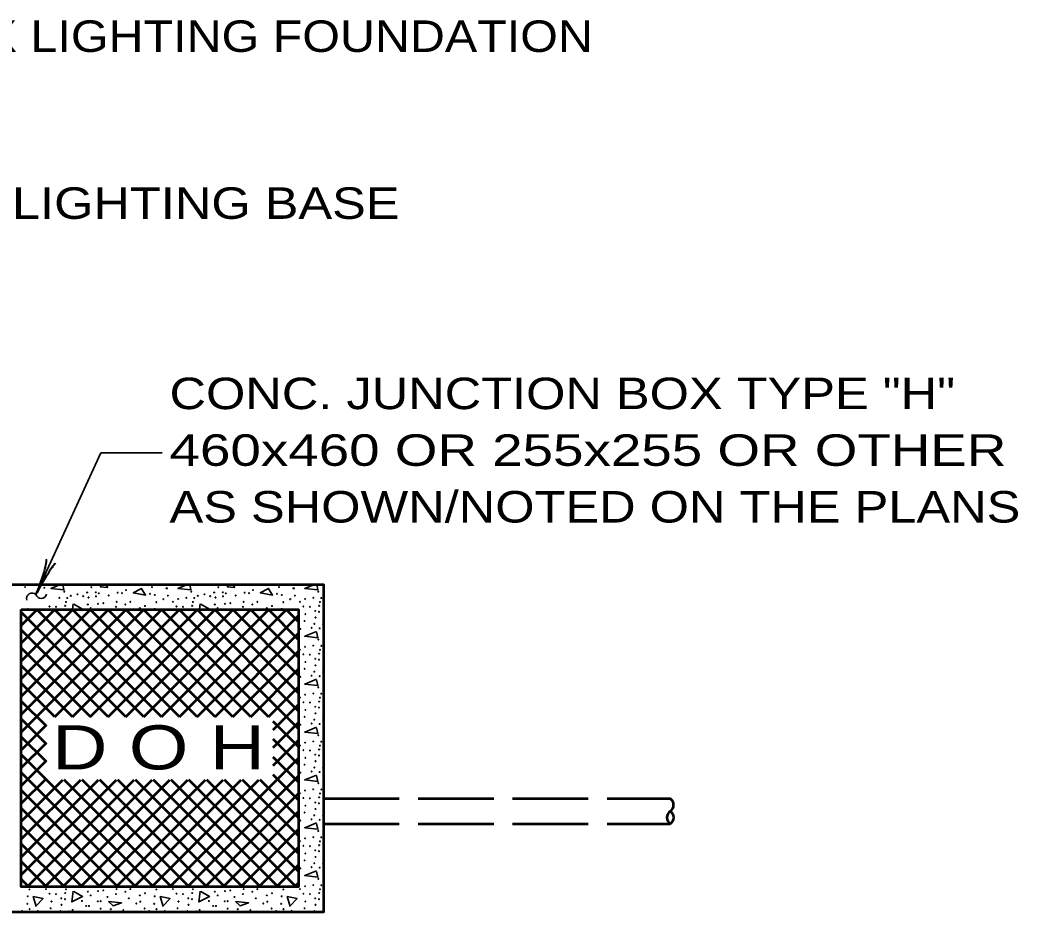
# Model space of a CAD drawing. Extents: x -24 to 689, y -7 to 446.
# Drawn here: x 391.4 to 470.6, y 78.6 to 149.4 of the extents above; entities that cross this region are included whole.
import ezdxf
from ezdxf.enums import TextEntityAlignment as Align

# ---------------------------------------------------------------- set-up
doc = ezdxf.new("R2010")
doc.units = 0
doc.linetypes.add('LONG_DASHED', pattern=[7.5, 6, -1.5])
doc.layers.add('1', color=7, linetype='Continuous', lineweight=35)

msp = doc.modelspace()

# ---------------------------------------------------------------- linework, layer by layer
at = {"layer": '1'}
for p, q in [((392.647, 103.805), (397.796, 115.046)), ((402.654, 115.046), (397.796, 115.046)), ((395.546, 102.608), (395.61, 103.056)), ((405.626, 102.608), (405.69, 103.056))]:
    msp.add_line(p, q, dxfattribs=at)
at = {"layer": '1', "lineweight": 53}
for p, q in [((391.486, 101.358), (392.736, 102.608)), ((391.486, 99.944), (394.15, 102.608)), ((391.486, 98.53), (395.564, 102.608)), ((391.486, 97.115), (396.979, 102.608)), ((391.486, 95.701), (398.393, 102.608)), ((391.486, 94.287), (399.807, 102.608)), ((391.486, 92.873), (401.221, 102.608)), ((399.795, 94.108), (391.486, 102.418)), ((401.21, 94.108), (392.71, 102.608)), ((402.624, 94.108), (394.124, 102.608)), ((394.135, 94.108), (402.635, 102.608)), ((404.038, 94.108), (395.538, 102.608)), ((395.55, 94.108), (404.05, 102.608)), ((405.452, 94.108), (396.952, 102.608)), ((396.964, 94.108), (405.464, 102.608)), ((406.866, 94.108), (398.366, 102.608)), ((398.378, 94.108), (406.878, 102.608)), ((408.281, 94.108), (399.781, 102.608)), ((399.792, 94.108), (408.292, 102.608)), ((409.695, 94.108), (401.195, 102.608)), ((401.207, 94.108), (409.707, 102.608)), ((411.109, 94.108), (402.609, 102.608)), ((402.621, 94.108), (411.121, 102.608)), ((413.486, 93.146), (404.023, 102.608)), ((404.035, 94.108), (412.535, 102.608)), ((413.486, 94.56), (405.438, 102.608)), ((413.486, 95.974), (406.852, 102.608)), ((413.486, 97.388), (408.266, 102.608)), ((413.486, 98.803), (409.68, 102.608)), ((413.486, 100.217), (411.094, 102.608)), ((413.486, 101.631), (412.509, 102.608)), ((405.449, 94.108), (413.486, 102.145)), ((398.381, 94.108), (391.486, 101.004)), ((406.863, 94.108), (413.486, 100.731)), ((396.967, 94.108), (391.486, 99.589)), ((408.278, 94.108), (413.486, 99.317)), ((395.553, 94.108), (391.486, 98.175)), ((409.692, 94.108), (413.486, 97.902)), ((394.138, 94.108), (391.486, 96.761)), ((411.106, 94.108), (413.486, 96.488)), ((393.486, 93.347), (391.486, 95.347)), ((411.486, 93.074), (413.486, 95.074)), ((393.486, 91.933), (391.486, 93.933)), ((413.486, 91.732), (411.486, 93.732)), ((411.486, 91.66), (413.486, 93.66)), ((391.486, 91.459), (393.486, 93.459)), ((393.486, 90.518), (391.486, 92.518)), ((391.486, 90.044), (393.486, 92.044)), ((413.486, 90.317), (411.486, 92.317)), ((411.486, 90.245), (413.486, 92.245)), ((401.982, 80.608), (391.486, 91.104)), ((391.486, 88.63), (393.486, 90.63)), ((403.263, 80.608), (413.486, 90.831)), ((413.486, 88.903), (411.486, 90.903)), ((400.567, 80.608), (391.486, 89.69)), ((391.486, 87.216), (393.486, 89.216)), ((391.486, 85.802), (394.792, 89.108)), ((391.486, 84.388), (396.207, 89.108)), ((391.486, 82.973), (397.621, 89.108)), ((391.486, 81.559), (399.035, 89.108)), ((391.949, 80.608), (400.449, 89.108)), ((393.363, 80.608), (401.863, 89.108)), ((394.778, 80.608), (403.278, 89.108)), ((403.396, 80.608), (394.896, 89.108)), ((396.192, 80.608), (404.692, 89.108)), ((404.81, 80.608), (396.31, 89.108)), ((397.606, 80.608), (406.106, 89.108)), ((406.224, 80.608), (397.724, 89.108)), ((399.02, 80.608), (407.52, 89.108)), ((407.638, 80.608), (399.138, 89.108)), ((400.435, 80.608), (408.935, 89.108)), ((409.053, 80.608), (400.553, 89.108)), ((401.849, 80.608), (410.349, 89.108)), ((410.467, 80.608), (401.967, 89.108)), ((411.881, 80.608), (403.381, 89.108)), ((404.677, 80.608), (413.486, 89.417)), ((413.295, 80.608), (404.795, 89.108)), ((413.486, 81.832), (406.21, 89.108)), ((413.486, 83.246), (407.624, 89.108)), ((413.486, 84.66), (409.038, 89.108)), ((413.486, 86.075), (410.452, 89.108)), ((413.486, 87.489), (411.486, 89.489)), ((399.153, 80.608), (391.486, 88.276)), ((406.091, 80.608), (413.486, 88.003)), ((397.739, 80.608), (391.486, 86.861)), ((407.506, 80.608), (413.486, 86.589)), ((396.325, 80.608), (391.486, 85.447)), ((408.92, 80.608), (413.486, 85.174)), ((394.911, 80.608), (391.486, 84.033)), ((410.334, 80.608), (413.486, 83.76)), ((393.496, 80.608), (391.486, 82.619)), ((411.748, 80.608), (413.486, 82.346)), ((392.082, 80.608), (391.486, 81.205)), ((413.162, 80.608), (413.486, 80.932))]:
    msp.add_line(p, q, dxfattribs=at)
at = {"layer": '1', "linetype": 'LONG_DASHED', "lineweight": 53}
for p, q in [((415.486, 87.608), (442.986, 87.608)), ((415.486, 85.608), (442.986, 85.608))]:
    msp.add_line(p, q, dxfattribs=at)
at = {"layer": '1', "lineweight": 53}
for points in [[(389.486, 78.608), (389.486, 104.608), (415.486, 104.608), (415.486, 78.608)], [(391.486, 102.608), (413.486, 102.608), (413.486, 80.608), (391.486, 80.608)]]:
    msp.add_lwpolyline(points, close=True, dxfattribs=at)
at = {"layer": '1'}
for points in [[(394.602, 104.608), (393.83, 104.296), (394.87, 104.176), (394.776, 104.608)], [(397.933, 104.608), (397.75, 104.416), (398.33, 104.376), (398.214, 104.608)], [(404.682, 104.608), (403.91, 104.296), (404.95, 104.176), (404.856, 104.608)], [(408.012, 104.608), (407.83, 104.416), (408.41, 104.376), (408.294, 104.608)], [(414.762, 104.608), (413.99, 104.296), (415.03, 104.176), (414.936, 104.608)], [(401.03, 104.296), (400.37, 103.936), (401.35, 103.756), (400.99, 104.316)], [(411.11, 104.296), (410.45, 103.936), (411.43, 103.756), (411.07, 104.316)], [(395.65, 103.036), (396.35, 102.636), (396.293, 102.608)], [(405.73, 103.036), (406.43, 102.636), (406.373, 102.608)], [(392.438, 102.608), (392.43, 102.636), (392.566, 102.608)], [(402.518, 102.608), (402.51, 102.636), (402.646, 102.608)], [(412.598, 102.608), (412.59, 102.636), (412.726, 102.608)], [(414.93, 100.876), (413.99, 100.496), (415.03, 100.376), (414.93, 100.836)], [(414.93, 97.076), (413.99, 96.696), (415.03, 96.576), (414.93, 97.036)], [(414.93, 93.276), (413.99, 92.896), (415.03, 92.776), (414.93, 93.236)], [(414.93, 89.476), (413.99, 89.096), (415.03, 88.976), (414.93, 89.436)], [(414.93, 85.676), (413.99, 85.296), (415.03, 85.176), (414.93, 85.636)], [(414.93, 81.876), (413.99, 81.496), (415.03, 81.376), (414.93, 81.836)], [(395.65, 80.236), (396.35, 79.836), (395.49, 79.416), (395.61, 80.256)], [(405.73, 80.236), (406.43, 79.836), (405.57, 79.416), (405.69, 80.256)], [(392.67, 79.036), (392.43, 79.836), (393.21, 79.676), (392.65, 79.076)], [(402.75, 79.036), (402.51, 79.836), (403.29, 79.676), (402.73, 79.076)], [(412.83, 79.036), (412.59, 79.836), (413.37, 79.676), (412.81, 79.076)]]:
    msp.add_lwpolyline(points, dxfattribs=at)
for points in [[(398.41, 79.456), (399.45, 79.336), (398.77, 79.096)], [(408.49, 79.456), (409.53, 79.336), (408.85, 79.096)]]:
    msp.add_lwpolyline(points, close=True, dxfattribs=at)
for centre in [(395.534, 104.555), (396.369, 104.568), (405.614, 104.555), (406.449, 104.568), (391.784, 104.396), (392.923, 104.303), (393.315, 104.345), (394.898, 104.038), (395.945, 103.826), (396.714, 103.972), (397.045, 104.383), (397.403, 103.985), (397.636, 103.906), (399.133, 103.959), (399.478, 103.919), (399.796, 104.158), (401.705, 103.866), (401.864, 104.396), (402.089, 103.773), (403.003, 104.303), (403.056, 104.303), (404.978, 104.038), (406.025, 103.826), (406.794, 103.972), (407.125, 104.383), (407.483, 103.985), (407.716, 103.906), (409.213, 103.959), (409.558, 103.919), (409.876, 104.158), (411.785, 103.866), (411.944, 104.396), (412.169, 103.773), (413.083, 104.303), (413.136, 104.303), (415.058, 104.038), (394.5, 103.548), (395.031, 103.216), (395.137, 103.534), (395.415, 103.707), (396.396, 103.68), (396.767, 103.017), (396.82, 103.574), (397.416, 103.667), (397.575, 103.07), (397.994, 103.123), (398.418, 103.733), (399.054, 103.229), (399.743, 103.017), (400.141, 103.229), (402.208, 103.203), (402.752, 103.442), (403.123, 103.72), (403.52, 103.229), (403.931, 103.455), (404.58, 103.548), (405.111, 103.216), (405.217, 103.534), (405.495, 103.707), (406.476, 103.68), (406.847, 103.017), (406.9, 103.574), (407.496, 103.667), (407.655, 103.07), (408.074, 103.123), (408.498, 103.733), (409.134, 103.229), (409.823, 103.017), (410.221, 103.229), (412.288, 103.203), (412.832, 103.442), (413.203, 103.72), (413.6, 103.229), (414.011, 103.455), (414.66, 103.548), (415.191, 103.216), (415.297, 103.534), (391.996, 102.659), (393.719, 102.858), (394.235, 102.832), (394.964, 102.911), (396.992, 102.726), (399.001, 102.832), (400.896, 102.726), (401.307, 102.898), (402.076, 102.659), (403.799, 102.858), (404.315, 102.832), (405.044, 102.911), (407.072, 102.726), (409.081, 102.832), (410.976, 102.726), (411.387, 102.898), (412.156, 102.659), (413.879, 102.858), (414.038, 102.248), (414.395, 102.832), (414.819, 102.5), (415.111, 102.434), (415.124, 102.911), (413.971, 101.705), (414.74, 101.48), (414.833, 101.983), (415.442, 101.453), (413.64, 101.073), (414.528, 101.166), (415.164, 101.126), (415.058, 100.238), (413.6, 99.429), (413.879, 99.058), (414.011, 99.655), (414.395, 99.032), (414.66, 99.748), (415.124, 99.111), (415.191, 99.416), (415.297, 99.734), (414.038, 98.448), (414.819, 98.7), (415.111, 98.634), (413.971, 97.905), (414.74, 97.68), (414.833, 98.183), (415.442, 97.653), (413.64, 97.273), (414.528, 97.366), (415.164, 97.326), (414.011, 95.855), (414.66, 95.948), (415.058, 96.438), (415.297, 95.934), (413.6, 95.629), (413.879, 95.258), (414.395, 95.232), (415.124, 95.311), (415.191, 95.616), (414.038, 94.648), (414.819, 94.9), (414.833, 94.383), (415.111, 94.834), (413.64, 93.473), (413.971, 94.105), (414.528, 93.566), (414.74, 93.88), (415.164, 93.526), (415.442, 93.853), (414.011, 92.055), (414.66, 92.148), (415.058, 92.638), (415.297, 92.134), (413.6, 91.829), (413.879, 91.458), (414.395, 91.432), (414.819, 91.1), (415.124, 91.511), (415.191, 91.816), (413.971, 90.305), (414.038, 90.848), (414.833, 90.583), (415.111, 91.034), (413.64, 89.673), (414.528, 89.766), (414.74, 90.08), (415.164, 89.726), (415.442, 90.053), (415.058, 88.838), (413.6, 88.029), (414.011, 88.255), (414.66, 88.348), (415.191, 88.016), (415.297, 88.334), (413.879, 87.658), (414.395, 87.632), (414.819, 87.3), (415.111, 87.234), (415.124, 87.711), (413.971, 86.505), (414.038, 87.048), (414.833, 86.783), (413.64, 85.873), (414.528, 85.966), (414.74, 86.28), (415.164, 85.926), (415.442, 86.253), (415.058, 85.038), (413.6, 84.229), (414.011, 84.455), (414.66, 84.548), (415.191, 84.216), (415.297, 84.534), (413.879, 83.858), (414.038, 83.248), (414.395, 83.832), (414.819, 83.5), (415.111, 83.434), (415.124, 83.911), (413.971, 82.705), (414.74, 82.48), (414.833, 82.983), (415.442, 82.453), (413.64, 82.073), (414.528, 82.166), (415.164, 82.126), (415.058, 81.238), (392.128, 80.403), (393.44, 80.429), (393.719, 80.058), (394.235, 80.032), (394.964, 80.111), (395.031, 80.416), (396.767, 80.217), (397.575, 80.27), (397.994, 80.323), (399.001, 80.032), (399.054, 80.429), (399.743, 80.217), (400.141, 80.429), (401.307, 80.098), (402.208, 80.403), (403.52, 80.429), (403.799, 80.058), (404.315, 80.032), (405.044, 80.111), (405.111, 80.416), (406.847, 80.217), (407.655, 80.27), (408.074, 80.323), (409.081, 80.032), (409.134, 80.429), (409.823, 80.217), (410.221, 80.429), (411.387, 80.098), (412.288, 80.403), (413.6, 80.429), (413.879, 80.058), (414.011, 80.655), (414.395, 80.032), (414.66, 80.748), (415.124, 80.111), (415.191, 80.416), (415.297, 80.734), (391.956, 79.263), (391.996, 79.859), (393.878, 79.448), (394.659, 79.7), (394.951, 79.634), (396.303, 79.488), (396.992, 79.926), (397.555, 79.459), (397.782, 79.475), (398.325, 79.806), (400.021, 79.7), (400.618, 79.289), (400.896, 79.926), (400.936, 79.435), (402.036, 79.263), (402.076, 79.859), (403.958, 79.448), (404.739, 79.7), (405.031, 79.634), (406.383, 79.488), (407.072, 79.926), (407.635, 79.459), (407.862, 79.475), (408.405, 79.806), (410.101, 79.7), (410.698, 79.289), (410.976, 79.926), (411.016, 79.435), (412.116, 79.263), (412.156, 79.859), (414.038, 79.448), (414.819, 79.7), (415.111, 79.634), (391.558, 78.693), (392.141, 78.839), (392.791, 78.693), (393.811, 78.905), (394.58, 78.68), (394.673, 79.183), (395.282, 78.653), (395.561, 78.772), (396.634, 79.09), (396.86, 79.09), (397.782, 78.878), (398.59, 78.839), (399.584, 78.759), (401.28, 78.892), (401.638, 78.693), (402.221, 78.839), (402.871, 78.693), (403.891, 78.905), (404.66, 78.68), (404.753, 79.183), (405.362, 78.653), (405.641, 78.772), (406.714, 79.09), (406.94, 79.09), (407.862, 78.878), (408.67, 78.839), (409.664, 78.759), (411.36, 78.892), (411.718, 78.693), (412.301, 78.839), (412.951, 78.693), (413.971, 78.905), (414.74, 78.68), (414.833, 79.183), (415.442, 78.653)]:
    msp.add_circle(centre, 0.0265, dxfattribs=at)
for centre, radius, start, end in [((391.624, 104.608), 0.0265, 179.8468, 0.1532), ((392.3, 104.608), 0.0265, 179.8468, 0.1532), ((401.704, 104.608), 0.0265, 179.8468, 0.1532), ((402.38, 104.608), 0.0265, 179.8468, 0.1532), ((411.784, 104.608), 0.0265, 179.8468, 0.1532), ((412.46, 104.608), 0.0265, 179.8468, 0.1532), ((392.344, 103.488), 0.439, 46.31832, 196.9194), ((393.068, 103.93), 0.439, 196.46709, 347.06816), ((398.325, 102.606), 0.0265, 4.24531, 175.75469), ((408.405, 102.606), 0.0265, 4.24531, 175.75469), ((396.343, 78.587), 0.0265, 54.86427, 125.13573), ((397.323, 78.6), 0.0265, 18.43349, 161.56651), ((406.423, 78.587), 0.0265, 54.86427, 125.13573), ((407.403, 78.6), 0.0265, 18.43349, 161.56651)]:
    msp.add_arc(centre, radius, start, end, dxfattribs=at)
at = {"layer": '1', "lineweight": 53}
for centre, radius, start, end in [((442.678, 87.108), 0.587, 301.63189, 58.3681), ((443.333, 86.108), 0.609, 124.76549, 235.23451), ((442.704, 86.108), 0.574, 299.39122, 60.60878)]:
    msp.add_arc(centre, radius, start, end, dxfattribs=at)
at = {"layer": '1', "lineweight": 40}
for centre, major_axis, ratio, start_param, end_param in [((392.85, 104.912), (-0.602, -1.688), 0.122415, 0.896353, 3.141593), ((392.85, 104.912), (-0.602, -1.688), 0.122415, 0.896353, 3.141593), ((393.306, 104.736), (-0.891, -1.524), 0.07063, 3.140715, 5.41811), ((393.306, 104.736), (-0.891, -1.524), 0.07063, 3.140715, 5.41811)]:
    msp.add_ellipse(centre, major_axis=major_axis, ratio=ratio, start_param=start_param, end_param=end_param, dxfattribs=at)

# ---------------------------------------------------------------- texts
at = {"layer": '1'}
for s, height, width, p in [('TYPE X LIGHTING FOUNDATION', 2.5, 1.15, (407.164, 146.868)), ('TYPE X LIGHTING BASE', 2.5, 1.2, (398.435, 133.62)), ('D O H', 3.5, 1.3, (402.384, 89.926))]:
    msp.add_text(s, height=height, dxfattribs=dict(at, width=width)).set_placement(p, align=Align.CENTER)
for s, width, p in [('CONC. JUNCTION BOX TYPE "H"', 1.2, (403.251, 118.519)), ('460x460 OR 255x255 OR OTHER', 1.3, (403.251, 114.019)), ('AS SHOWN/NOTED ON THE PLANS ', 1.2, (403.251, 109.519))]:
    msp.add_text(s, height=2.5, dxfattribs=dict(at, width=width)).set_placement(p)

doc.saveas('drawing.dxf')
